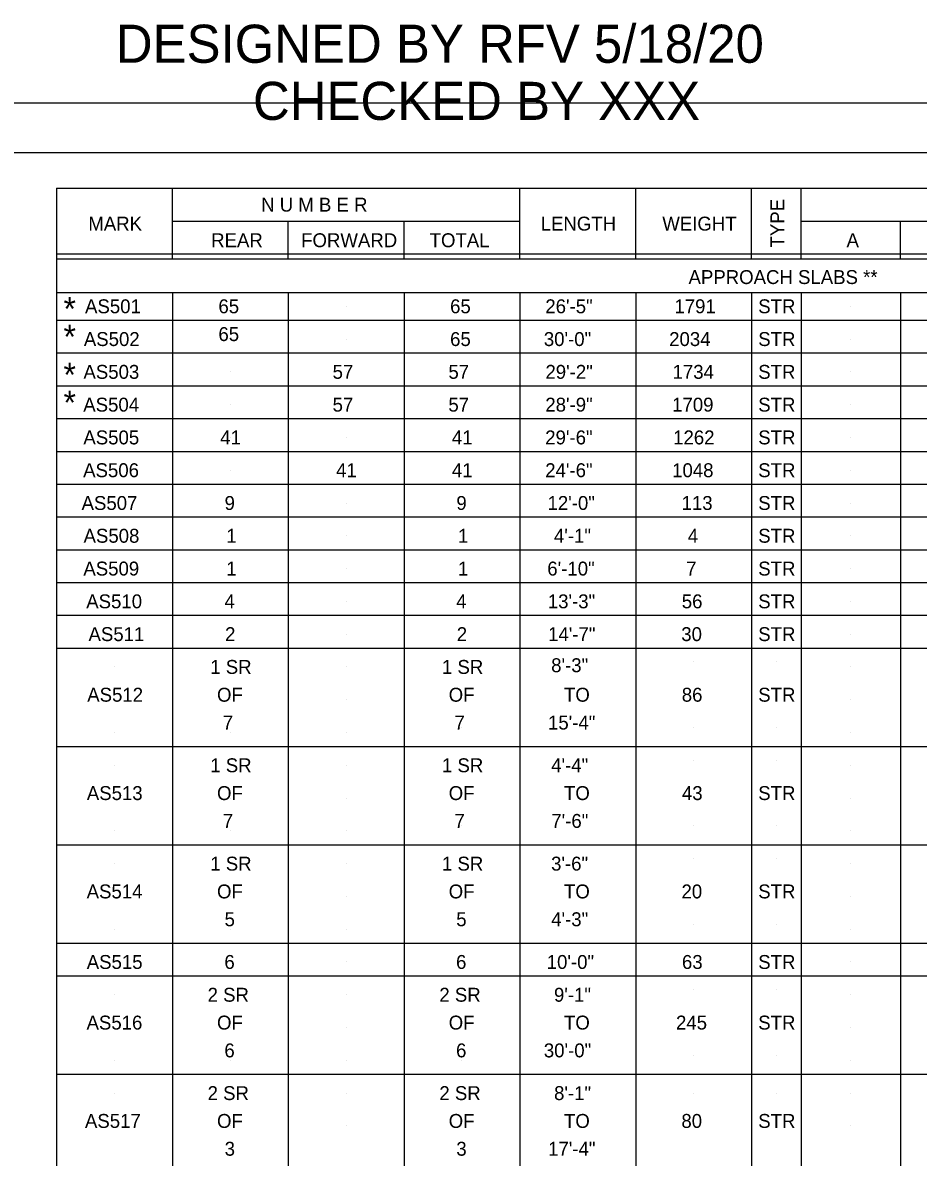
# Model space of a CAD drawing. Extents: x -31.1 to 2.9, y 8.5 to 31.4.
# Drawn here: x -15.02 to -6, y 19.87 to 31.29 of the extents above; entities that cross this region are included whole.
import ezdxf

# ---------------------------------------------------------------- set-up
doc = ezdxf.new("R2010")
doc.units = 0
for name, color, linetype in [('BR_P_Gen_Text', 7, 'Continuous'), ('Default', 7, 'Continuous'), ('SC_Scratch1', 7, 'Continuous'), ('SC_Scratch2', 7, 'Continuous')]:
    doc.layers.add(name, color=color, linetype=linetype)

msp = doc.modelspace()

# ---------------------------------------------------------------- linework, layer by layer
at = {"layer": 'BR_P_Gen_Text'}
for p, q in [((-14.678, 29.627), (-0.178, 29.627)), ((-13.511, 28.91), (-13.511, 29.627)), ((-10.011, 28.91), (-10.011, 29.627)), ((-8.845, 28.91), (-8.845, 29.627)), ((-7.678, 28.91), (-7.678, 29.627)), ((-7.178, 28.91), (-7.178, 29.627)), ((-13.511, 29.294), (-10.011, 29.294)), ((-11.178, 28.91), (-11.178, 29.294)), ((-7.178, 29.294), (-1.178, 29.294)), ((-6.178, 28.91), (-6.178, 29.294)), ((-0.178, 28.962), (-14.678, 28.962)), ((-1.523, 28.91), (-14.678, 28.91)), ((-0.178, 28.91), (-14.678, 28.91)), ((-14.678, 28.577), (-0.178, 28.577)), ((-14.678, 28.577), (-0.178, 28.577)), ((-13.511, 28.577), (-13.511, 11.467)), ((-12.345, 28.577), (-12.345, 11.467)), ((-11.178, 28.577), (-11.178, 11.467)), ((-10.011, 28.577), (-10.011, 11.467)), ((-8.845, 28.577), (-8.845, 11.467)), ((-7.678, 28.577), (-7.678, 11.467)), ((-7.178, 28.577), (-7.178, 11.467)), ((-6.178, 28.577), (-6.178, 11.467)), ((-14.678, 28.297), (-0.178, 28.297)), ((-14.678, 28.297), (-0.178, 28.297)), ((-14.678, 27.967), (-0.178, 27.967)), ((-14.678, 27.637), (-0.178, 27.637)), ((-14.678, 27.307), (-0.178, 27.307)), ((-14.678, 26.977), (-0.178, 26.977)), ((-14.678, 26.647), (-0.178, 26.647)), ((-14.678, 26.317), (-0.178, 26.317)), ((-14.678, 25.987), (-0.178, 25.987)), ((-14.678, 25.657), (-0.178, 25.657)), ((-14.678, 25.327), (-0.178, 25.327)), ((-14.678, 24.997), (-0.178, 24.997)), ((-14.678, 24.997), (-0.178, 24.997)), ((-14.678, 24.007), (-0.178, 24.007)), ((-14.678, 23.017), (-0.178, 23.017)), ((-14.678, 22.027), (-0.178, 22.027)), ((-14.678, 22.027), (-0.178, 22.027)), ((-14.678, 21.697), (-0.178, 21.697)), ((-14.678, 21.697), (-0.178, 21.697)), ((-14.678, 21.697), (-0.178, 21.697)), ((-14.678, 20.707), (-0.178, 20.707))]:
    msp.add_line(p, q, dxfattribs=at)
for points in [[(-31.128, 30.484), (2.872, 30.484), (2.872, 8.484), (-31.128, 8.484)], [(-29.128, 29.984), (1.372, 29.984), (1.372, 8.984), (-29.128, 8.984)]]:
    msp.add_lwpolyline(points, close=True, dxfattribs=at)
at = {"layer": 'Default'}
for p, q in [((-14.678, 29.627), (-14.678, 11.467)), ((-12.345, 28.91), (-12.345, 29.294))]:
    msp.add_line(p, q, dxfattribs=at)
at = {"layer": 'SC_Scratch1'}
for p, q in [((-14.095, 28.437), (-14.095, 28.437)), ((-14.095, 28.437), (-14.095, 28.437)), ((-14.095, 28.437), (-14.095, 28.437)), ((-12.928, 28.437), (-12.928, 28.437)), ((-12.928, 28.437), (-12.928, 28.437)), ((-12.928, 28.437), (-12.928, 28.437)), ((-11.761, 28.437), (-11.761, 28.437)), ((-11.761, 28.437), (-11.761, 28.437)), ((-10.595, 28.437), (-10.595, 28.437)), ((-9.407, 28.437), (-9.407, 28.437)), ((-8.261, 28.437), (-8.261, 28.437)), ((-7.428, 28.437), (-7.428, 28.437)), ((-6.678, 28.437), (-6.678, 28.437)), ((-6.678, 28.437), (-6.678, 28.437)), ((-14.095, 28.107), (-14.095, 28.107)), ((-14.095, 28.107), (-14.095, 28.107)), ((-12.928, 28.107), (-12.928, 28.107)), ((-11.761, 28.107), (-11.761, 28.107)), ((-11.761, 28.107), (-11.761, 28.107)), ((-10.595, 28.107), (-10.595, 28.107)), ((-9.407, 28.107), (-9.407, 28.107)), ((-8.261, 28.107), (-8.261, 28.107)), ((-7.428, 28.107), (-7.428, 28.107)), ((-6.678, 28.107), (-6.678, 28.107)), ((-6.678, 28.107), (-6.678, 28.107)), ((-14.095, 27.777), (-14.095, 27.777)), ((-14.095, 27.777), (-14.095, 27.777)), ((-12.928, 27.777), (-12.928, 27.777)), ((-11.761, 27.777), (-11.761, 27.777)), ((-11.761, 27.777), (-11.761, 27.777)), ((-10.595, 27.777), (-10.595, 27.777)), ((-9.407, 27.777), (-9.407, 27.777)), ((-8.261, 27.777), (-8.261, 27.777)), ((-7.428, 27.777), (-7.428, 27.777)), ((-6.678, 27.777), (-6.678, 27.777)), ((-6.678, 27.777), (-6.678, 27.777)), ((-14.095, 27.447), (-14.095, 27.447)), ((-14.095, 27.447), (-14.095, 27.447)), ((-12.928, 27.447), (-12.928, 27.447)), ((-11.761, 27.447), (-11.761, 27.447)), ((-10.595, 27.447), (-10.595, 27.447)), ((-9.407, 27.447), (-9.407, 27.447)), ((-8.261, 27.447), (-8.261, 27.447)), ((-7.428, 27.447), (-7.428, 27.447)), ((-6.678, 27.447), (-6.678, 27.447)), ((-6.678, 27.447), (-6.678, 27.447)), ((-14.095, 27.117), (-14.095, 27.117)), ((-14.095, 27.117), (-14.095, 27.117)), ((-12.928, 27.117), (-12.928, 27.117)), ((-11.761, 27.117), (-11.761, 27.117)), ((-10.595, 27.117), (-10.595, 27.117)), ((-9.407, 27.117), (-9.407, 27.117)), ((-8.261, 27.117), (-8.261, 27.117)), ((-7.428, 27.117), (-7.428, 27.117)), ((-6.678, 27.117), (-6.678, 27.117)), ((-6.678, 27.117), (-6.678, 27.117)), ((-14.095, 26.787), (-14.095, 26.787)), ((-14.095, 26.787), (-14.095, 26.787)), ((-12.928, 26.787), (-12.928, 26.787)), ((-11.761, 26.787), (-11.761, 26.787)), ((-10.595, 26.787), (-10.595, 26.787)), ((-9.407, 26.787), (-9.407, 26.787)), ((-8.261, 26.787), (-8.261, 26.787)), ((-7.428, 26.787), (-7.428, 26.787)), ((-6.678, 26.787), (-6.678, 26.787)), ((-6.678, 26.787), (-6.678, 26.787)), ((-14.095, 26.457), (-14.095, 26.457)), ((-14.095, 26.457), (-14.095, 26.457)), ((-12.928, 26.457), (-12.928, 26.457)), ((-11.761, 26.457), (-11.761, 26.457)), ((-10.595, 26.457), (-10.595, 26.457)), ((-9.407, 26.457), (-9.407, 26.457)), ((-8.261, 26.457), (-8.261, 26.457)), ((-7.428, 26.457), (-7.428, 26.457)), ((-6.678, 26.457), (-6.678, 26.457)), ((-6.678, 26.457), (-6.678, 26.457)), ((-14.095, 26.127), (-14.095, 26.127)), ((-14.095, 26.127), (-14.095, 26.127)), ((-12.928, 26.127), (-12.928, 26.127)), ((-11.761, 26.127), (-11.761, 26.127)), ((-10.595, 26.127), (-10.595, 26.127)), ((-9.407, 26.127), (-9.407, 26.127)), ((-8.261, 26.127), (-8.261, 26.127)), ((-7.428, 26.127), (-7.428, 26.127)), ((-6.678, 26.127), (-6.678, 26.127)), ((-6.678, 26.127), (-6.678, 26.127)), ((-14.095, 25.797), (-14.095, 25.797)), ((-14.095, 25.797), (-14.095, 25.797)), ((-12.928, 25.797), (-12.928, 25.797)), ((-11.761, 25.797), (-11.761, 25.797)), ((-10.595, 25.797), (-10.595, 25.797)), ((-9.407, 25.797), (-9.407, 25.797)), ((-8.261, 25.797), (-8.261, 25.797)), ((-7.428, 25.797), (-7.428, 25.797)), ((-6.678, 25.797), (-6.678, 25.797)), ((-6.678, 25.797), (-6.678, 25.797)), ((-14.095, 25.467), (-14.095, 25.467)), ((-14.095, 25.467), (-14.095, 25.467)), ((-12.928, 25.467), (-12.928, 25.467)), ((-11.761, 25.467), (-11.761, 25.467)), ((-10.595, 25.467), (-10.595, 25.467)), ((-9.407, 25.467), (-9.407, 25.467)), ((-8.261, 25.467), (-8.261, 25.467)), ((-7.428, 25.467), (-7.428, 25.467)), ((-6.678, 25.467), (-6.678, 25.467)), ((-6.678, 25.467), (-6.678, 25.467)), ((-14.095, 25.137), (-14.095, 25.137)), ((-12.928, 25.137), (-12.928, 25.137)), ((-11.761, 25.137), (-11.761, 25.137)), ((-10.595, 25.187), (-10.595, 25.187)), ((-9.407, 25.137), (-9.407, 25.137)), ((-8.261, 25.137), (-8.261, 25.137)), ((-7.428, 25.137), (-7.428, 25.137)), ((-6.678, 25.137), (-6.678, 25.137)), ((-14.095, 24.807), (-14.095, 24.807)), ((-12.928, 24.807), (-12.928, 24.807)), ((-11.761, 24.807), (-11.761, 24.807)), ((-10.595, 24.857), (-10.595, 24.857)), ((-9.407, 24.857), (-9.407, 24.857)), ((-8.261, 24.857), (-8.261, 24.857)), ((-7.428, 24.857), (-7.428, 24.857)), ((-6.678, 24.807), (-6.678, 24.807)), ((-14.095, 24.477), (-14.095, 24.477)), ((-12.928, 24.477), (-12.928, 24.477)), ((-11.761, 24.477), (-11.761, 24.477)), ((-10.595, 24.527), (-10.595, 24.527)), ((-9.407, 24.527), (-9.407, 24.527)), ((-8.261, 24.527), (-8.261, 24.527)), ((-7.428, 24.527), (-7.428, 24.527)), ((-6.678, 24.477), (-6.678, 24.477)), ((-14.095, 24.147), (-14.095, 24.147)), ((-12.928, 24.147), (-12.928, 24.147)), ((-11.761, 24.147), (-11.761, 24.147)), ((-10.595, 24.197), (-10.595, 24.197)), ((-9.407, 24.197), (-9.407, 24.197)), ((-8.261, 24.197), (-8.261, 24.197)), ((-7.428, 24.197), (-7.428, 24.197)), ((-6.678, 24.147), (-6.678, 24.147)), ((-14.095, 23.817), (-14.095, 23.817)), ((-12.928, 23.817), (-12.928, 23.817)), ((-11.761, 23.817), (-11.761, 23.817)), ((-10.595, 23.867), (-10.595, 23.867)), ((-9.407, 23.867), (-9.407, 23.867)), ((-8.261, 23.867), (-8.261, 23.867)), ((-7.428, 23.867), (-7.428, 23.867)), ((-6.678, 23.817), (-6.678, 23.817)), ((-10.595, 23.537), (-10.595, 23.537)), ((-9.407, 23.537), (-9.407, 23.537)), ((-8.261, 23.537), (-8.261, 23.537)), ((-7.428, 23.537), (-7.428, 23.537)), ((-14.095, 23.487), (-14.095, 23.487)), ((-12.928, 23.487), (-12.928, 23.487)), ((-11.761, 23.487), (-11.761, 23.487)), ((-6.678, 23.487), (-6.678, 23.487)), ((-10.595, 23.207), (-10.595, 23.207)), ((-9.407, 23.207), (-9.407, 23.207)), ((-8.261, 23.207), (-8.261, 23.207)), ((-7.428, 23.207), (-7.428, 23.207)), ((-14.095, 23.157), (-14.095, 23.157)), ((-12.928, 23.157), (-12.928, 23.157)), ((-11.761, 23.157), (-11.761, 23.157)), ((-6.678, 23.157), (-6.678, 23.157)), ((-10.595, 22.877), (-10.595, 22.877)), ((-9.407, 22.877), (-9.407, 22.877)), ((-8.261, 22.877), (-8.261, 22.877)), ((-7.428, 22.877), (-7.428, 22.877)), ((-14.095, 22.827), (-14.095, 22.827)), ((-12.928, 22.827), (-12.928, 22.827)), ((-11.761, 22.827), (-11.761, 22.827)), ((-6.678, 22.827), (-6.678, 22.827)), ((-10.595, 22.547), (-10.595, 22.547)), ((-9.407, 22.547), (-9.407, 22.547)), ((-8.261, 22.547), (-8.261, 22.547)), ((-7.428, 22.547), (-7.428, 22.547)), ((-14.095, 22.497), (-14.095, 22.497)), ((-12.928, 22.497), (-12.928, 22.497)), ((-11.761, 22.497), (-11.761, 22.497)), ((-6.678, 22.497), (-6.678, 22.497)), ((-14.095, 22.167), (-14.095, 22.167)), ((-12.928, 22.167), (-12.928, 22.167)), ((-11.761, 22.167), (-11.761, 22.167)), ((-10.595, 22.217), (-10.595, 22.217)), ((-9.407, 22.217), (-9.407, 22.217)), ((-8.261, 22.217), (-8.261, 22.217)), ((-7.428, 22.217), (-7.428, 22.217)), ((-6.678, 22.167), (-6.678, 22.167)), ((-14.095, 21.837), (-14.095, 21.837)), ((-12.928, 21.837), (-12.928, 21.837)), ((-11.761, 21.837), (-11.761, 21.837)), ((-10.595, 21.887), (-10.595, 21.887)), ((-9.407, 21.887), (-9.407, 21.887)), ((-8.261, 21.887), (-8.261, 21.887)), ((-7.428, 21.887), (-7.428, 21.887)), ((-6.678, 21.837), (-6.678, 21.837)), ((-14.095, 21.507), (-14.095, 21.507)), ((-12.928, 21.507), (-12.928, 21.507)), ((-11.761, 21.507), (-11.761, 21.507)), ((-10.595, 21.557), (-10.595, 21.557)), ((-9.407, 21.557), (-9.407, 21.557)), ((-8.261, 21.557), (-8.261, 21.557)), ((-7.428, 21.557), (-7.428, 21.557)), ((-6.678, 21.507), (-6.678, 21.507)), ((-14.095, 21.177), (-14.095, 21.177)), ((-14.095, 21.177), (-14.095, 21.177)), ((-12.928, 21.177), (-12.928, 21.177)), ((-11.761, 21.177), (-11.761, 21.177)), ((-10.595, 21.227), (-10.595, 21.227)), ((-10.595, 21.177), (-10.595, 21.177)), ((-9.407, 21.227), (-9.407, 21.227)), ((-8.261, 21.227), (-8.261, 21.227)), ((-7.428, 21.227), (-7.428, 21.227)), ((-6.678, 21.177), (-6.678, 21.177)), ((-14.095, 20.847), (-14.095, 20.847)), ((-14.095, 20.847), (-14.095, 20.847)), ((-14.095, 20.847), (-14.095, 20.847)), ((-12.928, 20.847), (-12.928, 20.847)), ((-11.761, 20.847), (-11.761, 20.847)), ((-10.595, 20.897), (-10.595, 20.897)), ((-10.595, 20.847), (-10.595, 20.847)), ((-9.407, 20.897), (-9.407, 20.897)), ((-8.261, 20.897), (-8.261, 20.897)), ((-7.428, 20.897), (-7.428, 20.897)), ((-6.678, 20.847), (-6.678, 20.847)), ((-6.678, 20.847), (-6.678, 20.847)), ((-14.095, 20.517), (-14.095, 20.517)), ((-14.095, 20.517), (-14.095, 20.517)), ((-12.928, 20.517), (-12.928, 20.517)), ((-11.761, 20.517), (-11.761, 20.517)), ((-10.595, 20.517), (-10.595, 20.517)), ((-9.407, 20.517), (-9.407, 20.517)), ((-9.407, 20.517), (-9.407, 20.517)), ((-8.261, 20.517), (-8.261, 20.517)), ((-8.261, 20.517), (-8.261, 20.517)), ((-7.428, 20.517), (-7.428, 20.517)), ((-7.428, 20.517), (-7.428, 20.517)), ((-6.678, 20.517), (-6.678, 20.517)), ((-6.678, 20.517), (-6.678, 20.517)), ((-14.095, 20.187), (-14.095, 20.187)), ((-12.928, 20.187), (-12.928, 20.187)), ((-11.761, 20.187), (-11.761, 20.187)), ((-10.595, 20.187), (-10.595, 20.187)), ((-9.407, 20.187), (-9.407, 20.187)), ((-9.407, 20.187), (-9.407, 20.187)), ((-8.261, 20.187), (-8.261, 20.187)), ((-8.261, 20.187), (-8.261, 20.187)), ((-7.428, 20.187), (-7.428, 20.187)), ((-7.428, 20.187), (-7.428, 20.187)), ((-6.678, 20.187), (-6.678, 20.187)), ((-6.678, 20.187), (-6.678, 20.187))]:
    msp.add_line(p, q, dxfattribs=at)

# ---------------------------------------------------------------- texts
at = {"layer": 'BR_P_Gen_Text'}
for s, height, p in [('*', 0.24, (-14.607, 28.291)), ('AS501', 0.14, (-14.39, 28.367)), ('65', 0.14, (-13.047, 28.367)), ('65', 0.14, (-10.714, 28.367)), ('26\'-5"', 0.14, (-9.755, 28.367)), ('1791', 0.14, (-8.455, 28.367)), ('STR', 0.14, (-7.611, 28.367)), ('*', 0.24, (-14.607, 28.011)), ('65', 0.14, (-13.047, 28.087)), ('AS502', 0.14, (-14.402, 28.037)), ('65', 0.14, (-10.714, 28.037)), ('30\'-0"', 0.14, (-9.77, 28.037)), ('2034', 0.14, (-8.508, 28.037)), ('STR', 0.14, (-7.611, 28.037)), ('*', 0.24, (-14.607, 27.628)), ('AS503', 0.14, (-14.406, 27.707)), ('57', 0.14, (-11.897, 27.707)), ('57', 0.14, (-10.731, 27.707)), ('29\'-2"', 0.14, (-9.754, 27.707)), ('1734', 0.14, (-8.474, 27.707)), ('STR', 0.14, (-7.611, 27.707)), ('*', 0.24, (-14.607, 27.348)), ('AS504', 0.14, (-14.408, 27.377)), ('57', 0.14, (-11.897, 27.377)), ('57', 0.14, (-10.731, 27.377)), ('28\'-9"', 0.14, (-9.755, 27.377)), ('1709', 0.14, (-8.478, 27.377)), ('STR', 0.14, (-7.611, 27.377)), ('AS505', 0.14, (-14.407, 27.047)), ('41', 0.14, (-13.029, 27.047)), ('41', 0.14, (-10.696, 27.047)), ('29\'-6"', 0.14, (-9.756, 27.047)), ('1262', 0.14, (-8.468, 27.047)), ('STR', 0.14, (-7.611, 27.047)), ('AS506', 0.14, (-14.409, 26.717)), ('41', 0.14, (-11.862, 26.717)), ('41', 0.14, (-10.696, 26.717)), ('24\'-6"', 0.14, (-9.756, 26.717)), ('1048', 0.14, (-8.478, 26.717)), ('STR', 0.14, (-7.611, 26.717)), ('AS507', 0.14, (-14.425, 26.387)), ('9', 0.14, (-12.985, 26.387)), ('9', 0.14, (-10.651, 26.387)), ('12\'-0"', 0.14, (-9.733, 26.387)), ('113', 0.14, (-8.383, 26.387)), ('STR', 0.14, (-7.611, 26.387)), ('AS508', 0.14, (-14.405, 26.057)), ('1', 0.14, (-12.968, 26.057)), ('1', 0.14, (-10.634, 26.057)), ('4\'-1"', 0.14, (-9.668, 26.057)), ('4', 0.14, (-8.32, 26.057)), ('STR', 0.14, (-7.611, 26.057)), ('AS509', 0.14, (-14.407, 25.727)), ('1', 0.14, (-12.968, 25.727)), ('1', 0.14, (-10.634, 25.727)), ('6\'-10"', 0.14, (-9.735, 25.727)), ('7', 0.14, (-8.337, 25.727)), ('STR', 0.14, (-7.611, 25.727)), ('AS510', 0.14, (-14.378, 25.397)), ('4', 0.14, (-12.986, 25.397)), ('4', 0.14, (-10.653, 25.397)), ('13\'-3"', 0.14, (-9.73, 25.397)), ('56', 0.14, (-8.381, 25.397)), ('STR', 0.14, (-7.611, 25.397)), ('AS511', 0.14, (-14.355, 25.067)), ('2', 0.14, (-12.98, 25.067)), ('2', 0.14, (-10.647, 25.067)), ('14\'-7"', 0.14, (-9.727, 25.067)), ('30', 0.14, (-8.386, 25.067)), ('STR', 0.14, (-7.611, 25.067)), ('1 SR', 0.14, (-13.129, 24.737)), ('1 SR', 0.14, (-10.796, 24.737)), ('8\'-3"', 0.14, (-9.696, 24.754)), ('AS512', 0.14, (-14.368, 24.457)), ('OF', 0.14, (-13.061, 24.457)), ('OF', 0.14, (-10.728, 24.457)), ('TO', 0.14, (-9.567, 24.457)), ('86', 0.14, (-8.381, 24.457)), ('STR', 0.14, (-7.611, 24.457)), ('7', 0.14, (-13.003, 24.177)), ('7', 0.14, (-10.67, 24.177)), ('15\'-4"', 0.14, (-9.728, 24.177)), ('1 SR', 0.14, (-13.129, 23.747)), ('1 SR', 0.14, (-10.796, 23.747)), ('4\'-4"', 0.14, (-9.696, 23.747)), ('AS513', 0.14, (-14.372, 23.467)), ('OF', 0.14, (-13.061, 23.467)), ('OF', 0.14, (-10.728, 23.467)), ('TO', 0.14, (-9.567, 23.467)), ('43', 0.14, (-8.379, 23.467)), ('STR', 0.14, (-7.611, 23.467)), ('7', 0.14, (-13.003, 23.187)), ('7', 0.14, (-10.67, 23.187)), ('7\'-6"', 0.14, (-9.695, 23.187)), ('1 SR', 0.14, (-13.129, 22.757)), ('1 SR', 0.14, (-10.796, 22.757)), ('3\'-6"', 0.14, (-9.697, 22.757)), ('AS514', 0.14, (-14.374, 22.477)), ('OF', 0.14, (-13.061, 22.477)), ('OF', 0.14, (-10.728, 22.477)), ('TO', 0.14, (-9.567, 22.477)), ('20', 0.14, (-8.384, 22.477)), ('STR', 0.14, (-7.611, 22.477)), ('5', 0.14, (-12.985, 22.197)), ('5', 0.14, (-10.652, 22.197)), ('4\'-3"', 0.14, (-9.696, 22.197)), ('AS515', 0.14, (-14.373, 21.767)), ('6', 0.14, (-12.987, 21.767)), ('6', 0.14, (-10.654, 21.767)), ('10\'-0"', 0.14, (-9.741, 21.767)), ('63', 0.14, (-8.379, 21.767)), ('STR', 0.14, (-7.611, 21.767)), ('2 SR', 0.14, (-13.156, 21.437)), ('2 SR', 0.14, (-10.822, 21.437)), ('9\'-1"', 0.14, (-9.668, 21.437)), ('AS516', 0.14, (-14.375, 21.157)), ('OF', 0.14, (-13.061, 21.157)), ('OF', 0.14, (-10.728, 21.157)), ('TO', 0.14, (-9.567, 21.157)), ('245', 0.14, (-8.439, 21.157)), ('STR', 0.14, (-7.611, 21.157)), ('6', 0.14, (-12.987, 20.877)), ('6', 0.14, (-10.654, 20.877)), ('30\'-0"', 0.14, (-9.77, 20.877)), ('2 SR', 0.14, (-13.156, 20.447)), ('2 SR', 0.14, (-10.822, 20.447)), ('8\'-1"', 0.14, (-9.667, 20.447)), ('AS517', 0.14, (-14.391, 20.167)), ('OF', 0.14, (-13.061, 20.167)), ('OF', 0.14, (-10.728, 20.167)), ('TO', 0.14, (-9.567, 20.167)), ('80', 0.14, (-8.385, 20.167)), ('STR', 0.14, (-7.611, 20.167)), ('3', 0.14, (-12.984, 19.887)), ('3', 0.14, (-10.651, 19.887)), ('17\'-4"', 0.14, (-9.727, 19.887))]:
    msp.add_text(s, height=height, dxfattribs=at).set_placement(p)
at = {"layer": 'Default'}
for s, p in [('N U M B E R', (-12.617, 29.39)), ('MARK', (-14.357, 29.199)), ('LENGTH', (-9.802, 29.199)), ('WEIGHT', (-8.577, 29.199)), ('REAR', (-13.12, 29.032)), ('FORWARD', (-12.214, 29.032)), ('TOTAL', (-10.92, 29.032)), ('A', (-6.722, 29.032)), ('APPROACH SLABS **', (-8.313, 28.661))]:
    msp.add_text(s, height=0.14, dxfattribs=at).set_placement(p)
msp.add_text('TYPE', height=0.14, rotation=90, dxfattribs=at).set_placement((-7.348, 29.029))
at = {"layer": 'SC_Scratch2'}
for s, p in [('DESIGNED BY RFV 5/18/20', (-14.08, 30.888)), ('CHECKED BY XXX', (-12.699, 30.313))]:
    msp.add_text(s, height=0.38343, dxfattribs=at).set_placement(p)

doc.saveas('drawing.dxf')
